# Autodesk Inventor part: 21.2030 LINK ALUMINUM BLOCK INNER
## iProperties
Created: 2007-01
Part Number: 21.2030 LINK ALUMINUM BLOCK INNER
Material: Aluminum-6061
Document SubType Name: Modeling
Designer: Andy Moles
Density: 2.71 g/cm^3
Author: Andy Moles
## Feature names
1. Base1
2. Hole1
